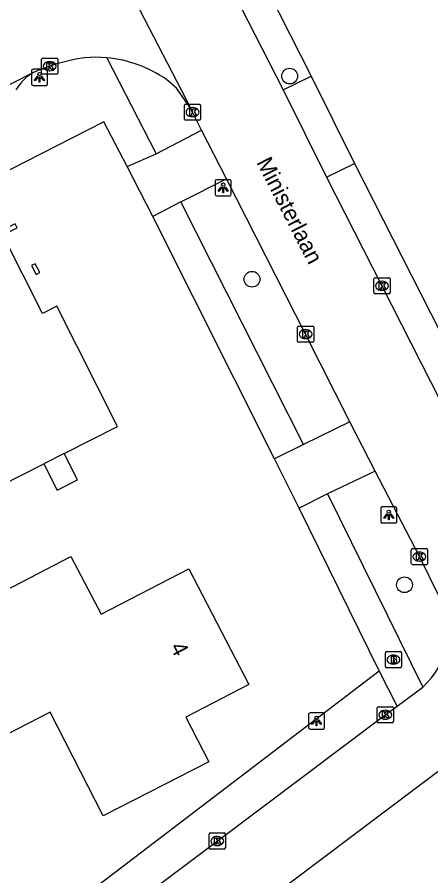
# Model space of a CAD drawing. Extents: x 162722 to 165099, y 384721 to 386283.
# Drawn here: x 163676.9 to 163702.6, y 384930.1 to 384983.4 of the extents above; entities that cross this region are included whole.
import ezdxf

# ---------------------------------------------------------------- set-up
doc = ezdxf.new("R2010")
doc.units = 0
for name, color, linetype in [('IMGEO_Boom', 7, 'Continuous'), ('IMGEO_Brandkraan', 7, 'Continuous'), ('IMGEO_Kolk', 7, 'Continuous'), ('IMGEO_Lichtpunt', 7, 'Continuous'), ('IMGEO_Openbare_ruimte_label', 7, 'Continuous'), ('IMGEO_Pand', 7, 'Continuous'), ('IMGEO_Pand_nummerreeks', 7, 'Continuous'), ('IMGEO_Parkeervlak_open', 7, 'Continuous'), ('IMGEO_Rijbaan_lokaal_open', 7, 'Continuous'), ('IMGEO_Voetpad_open', 7, 'Continuous')]:
    doc.layers.add(name, color=color, linetype=linetype)

msp = doc.modelspace()

# ---------------------------------------------------------------- linework, layer by layer
at = {"layer": 'IMGEO_Boom'}
for centre in [(163693.809, 384979.719), (163691.473, 384967.11), (163700.934, 384948.148)]:
    msp.add_circle(centre, 0.489, dxfattribs=at)
at = {"layer": 'IMGEO_Brandkraan'}
for p, q in [((163699.823, 384944.001), (163700.675, 384944.001)), ((163699.748, 384943.075), (163699.748, 384943.927)), ((163700.236, 384943.781), (163700.261, 384943.781)), ((163700.749, 384943.927), (163700.749, 384943.075)), ((163700.675, 384943.001), (163699.823, 384943.001)), ((163700.259, 384943.221), (163700.234, 384943.221))]:
    msp.add_line(p, q, dxfattribs=at)
for points in [[(163699.823, 384944.001), (163700.675, 384944.001)], [(163699.748, 384943.075), (163699.748, 384943.927)], [(163700.096, 384943.701), (163700.096, 384943.301), (163700.309, 384943.301)], [(163700.327, 384943.701), (163700.096, 384943.701)], [(163700.275, 384943.62), (163700.221, 384943.62), (163700.221, 384943.544)], [(163700.221, 384943.544), (163700.274, 384943.544)], [(163700.283, 384943.468), (163700.221, 384943.468), (163700.221, 384943.387)], [(163700.749, 384943.927), (163700.749, 384943.075)], [(163700.675, 384943.001), (163699.823, 384943.001)], [(163700.221, 384943.387), (163700.283, 384943.387)]]:
    msp.add_lwpolyline(points, dxfattribs=at)
for centre, radius, start, end in [((163699.825, 384943.925), 0.0765, 91.552, 178.448), ((163699.825, 384943.925), 0.0765, 91.552, 178.448), ((163700.673, 384943.925), 0.0765, 1.552, 88.448), ((163700.673, 384943.925), 0.0765, 1.552, 88.448), ((163700.276, 384943.582), 0.0379, 267.8285, 90.9355), ((163700.284, 384943.427), 0.0404, 269.8759, 90.5077), ((163700.331, 384943.556), 0.145, 59.4692, 91.5367), ((163700.356, 384943.603), 0.0922, 285.5137, 58.1501), ((163700.361, 384943.411), 0.105, 301.3115, 78.989), ((163699.825, 384943.077), 0.0765, 181.552, 268.448), ((163699.825, 384943.077), 0.0765, 181.552, 268.448), ((163700.315, 384943.552), 0.251, 268.6676, 293.5347), ((163700.673, 384943.077), 0.0765, 271.552, 358.448), ((163700.673, 384943.077), 0.0765, 271.552, 358.448)]:
    msp.add_arc(centre, radius, start, end, dxfattribs=at)
for centre, major_axis, ratio, start_param, end_param in [((163700.235, 384943.501), (-0.387, 0.002), 0.722429, 4.712389, 7.853982), ((163700.26, 384943.501), (-0.39, 0.002), 0.717154, 1.570796, 4.712389)]:
    msp.add_ellipse(centre, major_axis=major_axis, ratio=ratio, start_param=start_param, end_param=end_param, dxfattribs=at)
at = {"layer": 'IMGEO_Kolk'}
for p, q in [((163678.427, 384979.908), (163678.427, 384980.76)), ((163678.502, 384980.834), (163679.354, 384980.834)), ((163679.428, 384980.76), (163679.428, 384979.908)), ((163678.915, 384980.614), (163678.94, 384980.614)), ((163679.354, 384979.834), (163678.502, 384979.834)), ((163678.938, 384980.054), (163678.913, 384980.054)), ((163687.288, 384977.056), (163687.288, 384977.908)), ((163687.363, 384977.982), (163688.215, 384977.982)), ((163687.776, 384977.762), (163687.801, 384977.762)), ((163688.289, 384977.908), (163688.289, 384977.056)), ((163688.215, 384976.982), (163687.363, 384976.982)), ((163687.799, 384977.202), (163687.774, 384977.202)), ((163699.033, 384966.278), (163699.033, 384967.13)), ((163699.108, 384967.204), (163699.96, 384967.204)), ((163699.521, 384966.984), (163699.546, 384966.984)), ((163700.034, 384967.13), (163700.034, 384966.278)), ((163699.544, 384966.424), (163699.519, 384966.424)), ((163699.96, 384966.204), (163699.108, 384966.204)), ((163694.375, 384964.202), (163695.227, 384964.202)), ((163694.3, 384963.276), (163694.3, 384964.128)), ((163694.788, 384963.982), (163694.813, 384963.982)), ((163695.301, 384964.128), (163695.301, 384963.276)), ((163695.227, 384963.202), (163694.375, 384963.202)), ((163694.811, 384963.422), (163694.786, 384963.422)), ((163701.43, 384950.395), (163702.282, 384950.395)), ((163701.355, 384949.469), (163701.355, 384950.321)), ((163701.843, 384950.175), (163701.868, 384950.175)), ((163702.356, 384950.321), (163702.356, 384949.469)), ((163702.282, 384949.395), (163701.43, 384949.395)), ((163701.866, 384949.615), (163701.841, 384949.615)), ((163699.239, 384939.655), (163699.239, 384940.507)), ((163699.314, 384940.581), (163700.166, 384940.581)), ((163699.727, 384940.361), (163699.752, 384940.361)), ((163700.24, 384940.507), (163700.24, 384939.655)), ((163699.75, 384939.801), (163699.725, 384939.801)), ((163700.166, 384939.581), (163699.314, 384939.581)), ((163688.895, 384932.743), (163689.747, 384932.743)), ((163688.82, 384931.817), (163688.82, 384932.669)), ((163689.308, 384932.523), (163689.333, 384932.523)), ((163689.821, 384932.669), (163689.821, 384931.817)), ((163689.747, 384931.743), (163688.895, 384931.743)), ((163689.331, 384931.963), (163689.306, 384931.963))]:
    msp.add_line(p, q, dxfattribs=at)
for points in [[(163678.427, 384979.908), (163678.427, 384980.76)], [(163678.502, 384980.834), (163679.354, 384980.834)], [(163679.428, 384980.76), (163679.428, 384979.908)], [(163678.748, 384980.534), (163678.871, 384980.534), (163678.871, 384980.383), (163679.001, 384980.534), (163679.165, 384980.534), (163679.019, 384980.383), (163679.172, 384980.134), (163679.02, 384980.134), (163678.935, 384980.298), (163678.871, 384980.231), (163678.871, 384980.134), (163678.748, 384980.134), (163678.748, 384980.534)], [(163679.354, 384979.834), (163678.502, 384979.834)], [(163687.288, 384977.056), (163687.288, 384977.908)], [(163687.363, 384977.982), (163688.215, 384977.982)], [(163687.609, 384977.682), (163687.732, 384977.682), (163687.732, 384977.531), (163687.862, 384977.682), (163688.026, 384977.682), (163687.88, 384977.531), (163688.033, 384977.282), (163687.881, 384977.282), (163687.796, 384977.446), (163687.732, 384977.379), (163687.732, 384977.282), (163687.609, 384977.282), (163687.609, 384977.682)], [(163688.289, 384977.908), (163688.289, 384977.056)], [(163688.215, 384976.982), (163687.363, 384976.982)], [(163699.033, 384966.278), (163699.033, 384967.13)], [(163699.108, 384967.204), (163699.96, 384967.204)], [(163699.354, 384966.904), (163699.477, 384966.904), (163699.477, 384966.753), (163699.607, 384966.904), (163699.771, 384966.904), (163699.625, 384966.753), (163699.778, 384966.504), (163699.626, 384966.504), (163699.541, 384966.668), (163699.477, 384966.601), (163699.477, 384966.504), (163699.354, 384966.504), (163699.354, 384966.904)], [(163700.034, 384967.13), (163700.034, 384966.278)], [(163699.96, 384966.204), (163699.108, 384966.204)], [(163694.375, 384964.202), (163695.227, 384964.202)], [(163694.3, 384963.276), (163694.3, 384964.128)], [(163694.621, 384963.902), (163694.744, 384963.902), (163694.744, 384963.751), (163694.874, 384963.902), (163695.038, 384963.902), (163694.892, 384963.751), (163695.045, 384963.502), (163694.893, 384963.502), (163694.808, 384963.666), (163694.744, 384963.599), (163694.744, 384963.502), (163694.621, 384963.502), (163694.621, 384963.902)], [(163695.301, 384964.128), (163695.301, 384963.276)], [(163695.227, 384963.202), (163694.375, 384963.202)], [(163701.43, 384950.395), (163702.282, 384950.395)], [(163701.355, 384949.469), (163701.355, 384950.321)], [(163701.676, 384950.095), (163701.799, 384950.095), (163701.799, 384949.944), (163701.929, 384950.095), (163702.093, 384950.095), (163701.947, 384949.944), (163702.1, 384949.695), (163701.948, 384949.695), (163701.863, 384949.859), (163701.799, 384949.792), (163701.799, 384949.695), (163701.676, 384949.695), (163701.676, 384950.095)], [(163702.356, 384950.321), (163702.356, 384949.469)], [(163702.282, 384949.395), (163701.43, 384949.395)], [(163699.239, 384939.655), (163699.239, 384940.507)], [(163699.314, 384940.581), (163700.166, 384940.581)], [(163699.56, 384940.281), (163699.683, 384940.281), (163699.683, 384940.13), (163699.813, 384940.281), (163699.977, 384940.281), (163699.831, 384940.13), (163699.984, 384939.881), (163699.832, 384939.881), (163699.747, 384940.045), (163699.683, 384939.978), (163699.683, 384939.881), (163699.56, 384939.881), (163699.56, 384940.281)], [(163700.24, 384940.507), (163700.24, 384939.655)], [(163700.166, 384939.581), (163699.314, 384939.581)], [(163688.895, 384932.743), (163689.747, 384932.743)], [(163688.82, 384931.817), (163688.82, 384932.669)], [(163689.141, 384932.443), (163689.264, 384932.443), (163689.264, 384932.292), (163689.394, 384932.443), (163689.558, 384932.443), (163689.412, 384932.292), (163689.565, 384932.043), (163689.413, 384932.043), (163689.328, 384932.207), (163689.264, 384932.14), (163689.264, 384932.043), (163689.141, 384932.043), (163689.141, 384932.443)], [(163689.821, 384932.669), (163689.821, 384931.817)], [(163689.747, 384931.743), (163688.895, 384931.743)]]:
    msp.add_lwpolyline(points, dxfattribs=at)
for centre, start, end in [((163678.504, 384980.758), 91.552, 178.448), ((163678.504, 384980.758), 91.552, 178.448), ((163679.352, 384980.758), 1.552, 88.448), ((163679.352, 384980.758), 1.552, 88.448), ((163678.504, 384979.91), 181.552, 268.448), ((163678.504, 384979.91), 181.552, 268.448), ((163679.352, 384979.91), 271.552, 358.448), ((163679.352, 384979.91), 271.552, 358.448), ((163687.365, 384977.906), 91.552, 178.448), ((163687.365, 384977.906), 91.552, 178.448), ((163688.213, 384977.906), 1.552, 88.448), ((163688.213, 384977.906), 1.552, 88.448), ((163687.365, 384977.058), 181.552, 268.448), ((163687.365, 384977.058), 181.552, 268.448), ((163688.213, 384977.058), 271.552, 358.448), ((163688.213, 384977.058), 271.552, 358.448), ((163699.11, 384967.128), 91.552, 178.448), ((163699.11, 384967.128), 91.552, 178.448), ((163699.958, 384967.128), 1.552, 88.448), ((163699.958, 384967.128), 1.552, 88.448), ((163699.11, 384966.28), 181.552, 268.448), ((163699.11, 384966.28), 181.552, 268.448), ((163699.958, 384966.28), 271.552, 358.448), ((163699.958, 384966.28), 271.552, 358.448), ((163694.377, 384964.126), 91.552, 178.448), ((163694.377, 384964.126), 91.552, 178.448), ((163695.225, 384964.126), 1.552, 88.448), ((163695.225, 384964.126), 1.552, 88.448), ((163694.377, 384963.278), 181.552, 268.448), ((163694.377, 384963.278), 181.552, 268.448), ((163695.225, 384963.278), 271.552, 358.448), ((163695.225, 384963.278), 271.552, 358.448), ((163701.432, 384950.319), 91.552, 178.448), ((163701.432, 384950.319), 91.552, 178.448), ((163702.28, 384950.319), 1.552, 88.448), ((163702.28, 384950.319), 1.552, 88.448), ((163701.432, 384949.471), 181.552, 268.448), ((163701.432, 384949.471), 181.552, 268.448), ((163702.28, 384949.471), 271.552, 358.448), ((163702.28, 384949.471), 271.552, 358.448), ((163699.316, 384940.505), 91.552, 178.448), ((163699.316, 384940.505), 91.552, 178.448), ((163700.164, 384940.505), 1.552, 88.448), ((163700.164, 384940.505), 1.552, 88.448), ((163699.316, 384939.657), 181.552, 268.448), ((163699.316, 384939.657), 181.552, 268.448), ((163700.164, 384939.657), 271.552, 358.448), ((163700.164, 384939.657), 271.552, 358.448), ((163688.897, 384932.667), 91.552, 178.448), ((163688.897, 384932.667), 91.552, 178.448), ((163689.745, 384932.667), 1.552, 88.448), ((163689.745, 384932.667), 1.552, 88.448), ((163688.897, 384931.819), 181.552, 268.448), ((163688.897, 384931.819), 181.552, 268.448), ((163689.745, 384931.819), 271.552, 358.448), ((163689.745, 384931.819), 271.552, 358.448)]:
    msp.add_arc(centre, 0.0765, start, end, dxfattribs=at)
for centre, major_axis, ratio, start_param, end_param in [((163678.914, 384980.334), (-0.387, 0.002), 0.722429, 4.712389, 7.853982), ((163678.939, 384980.334), (-0.39, 0.002), 0.717154, 1.570796, 4.712389), ((163687.775, 384977.482), (-0.387, 0.002), 0.722429, 4.712389, 7.853982), ((163687.8, 384977.482), (-0.39, 0.002), 0.717154, 1.570796, 4.712389), ((163699.52, 384966.704), (-0.387, 0.002), 0.722429, 4.712389, 7.853982), ((163699.545, 384966.704), (-0.39, 0.002), 0.717154, 1.570796, 4.712389), ((163694.787, 384963.702), (-0.387, 0.002), 0.722429, 4.712389, 7.853982), ((163694.812, 384963.702), (-0.39, 0.002), 0.717154, 1.570796, 4.712389), ((163701.842, 384949.895), (-0.387, 0.002), 0.722429, 4.712389, 7.853982), ((163701.867, 384949.895), (-0.39, 0.002), 0.717154, 1.570796, 4.712389), ((163699.726, 384940.081), (-0.387, 0.002), 0.722429, 4.712389, 7.853982), ((163699.751, 384940.081), (-0.39, 0.002), 0.717154, 1.570796, 4.712389), ((163689.307, 384932.243), (-0.387, 0.002), 0.722429, 4.712389, 7.853982), ((163689.332, 384932.243), (-0.39, 0.002), 0.717154, 1.570796, 4.712389)]:
    msp.add_ellipse(centre, major_axis=major_axis, ratio=ratio, start_param=start_param, end_param=end_param, dxfattribs=at)
at = {"layer": 'IMGEO_Lichtpunt'}
for p, q in [((163677.802, 384980.045), (163677.802, 384979.238)), ((163677.802, 384980.045), (163677.802, 384979.238)), ((163678.704, 384980.14), (163677.896, 384980.14)), ((163678.704, 384980.14), (163677.896, 384980.14)), ((163678.798, 384979.238), (163678.798, 384980.045)), ((163678.798, 384979.238), (163678.798, 384980.045)), ((163677.896, 384979.144), (163678.704, 384979.144)), ((163677.896, 384979.144), (163678.704, 384979.144)), ((163690.091, 384973.283), (163689.283, 384973.283)), ((163690.091, 384973.283), (163689.283, 384973.283)), ((163689.189, 384973.188), (163689.189, 384972.381)), ((163689.189, 384973.188), (163689.189, 384972.381)), ((163690.185, 384972.381), (163690.185, 384973.188)), ((163690.185, 384972.381), (163690.185, 384973.188)), ((163689.283, 384972.287), (163690.091, 384972.287)), ((163689.283, 384972.287), (163690.091, 384972.287)), ((163699.459, 384952.883), (163699.459, 384952.076)), ((163699.459, 384952.883), (163699.459, 384952.076)), ((163700.361, 384952.978), (163699.553, 384952.978)), ((163700.361, 384952.978), (163699.553, 384952.978)), ((163700.455, 384952.076), (163700.455, 384952.883)), ((163700.455, 384952.076), (163700.455, 384952.883)), ((163699.553, 384951.982), (163700.361, 384951.982)), ((163699.553, 384951.982), (163700.361, 384951.982)), ((163694.981, 384940.096), (163694.981, 384939.289)), ((163694.981, 384940.096), (163694.981, 384939.289)), ((163695.883, 384940.191), (163695.075, 384940.191)), ((163695.883, 384940.191), (163695.075, 384940.191)), ((163695.977, 384939.289), (163695.977, 384940.096)), ((163695.977, 384939.289), (163695.977, 384940.096)), ((163695.075, 384939.195), (163695.883, 384939.195)), ((163695.075, 384939.195), (163695.883, 384939.195))]:
    msp.add_line(p, q, dxfattribs=at)
for points in [[(163678.176, 384979.709), (163678.215, 384979.681), (163678.027, 384979.419), (163677.989, 384979.446), (163678.176, 384979.709)], [(163678.278, 384979.661), (163678.325, 384979.661), (163678.325, 384979.339), (163678.278, 384979.339), (163678.278, 384979.661)], [(163678.388, 384979.681), (163678.426, 384979.708), (163678.613, 384979.446), (163678.574, 384979.418), (163678.388, 384979.681)], [(163689.563, 384972.852), (163689.602, 384972.824), (163689.414, 384972.562), (163689.376, 384972.589), (163689.563, 384972.852)], [(163689.665, 384972.804), (163689.712, 384972.804), (163689.712, 384972.482), (163689.665, 384972.482), (163689.665, 384972.804)], [(163689.775, 384972.824), (163689.813, 384972.851), (163690, 384972.589), (163689.961, 384972.561), (163689.775, 384972.824)], [(163699.833, 384952.547), (163699.872, 384952.519), (163699.684, 384952.257), (163699.646, 384952.284), (163699.833, 384952.547)], [(163699.935, 384952.499), (163699.982, 384952.499), (163699.982, 384952.177), (163699.935, 384952.177), (163699.935, 384952.499)], [(163700.045, 384952.519), (163700.083, 384952.546), (163700.27, 384952.284), (163700.231, 384952.256), (163700.045, 384952.519)], [(163695.355, 384939.76), (163695.394, 384939.732), (163695.206, 384939.47), (163695.168, 384939.497), (163695.355, 384939.76)], [(163695.457, 384939.712), (163695.504, 384939.712), (163695.504, 384939.39), (163695.457, 384939.39), (163695.457, 384939.712)], [(163695.567, 384939.732), (163695.605, 384939.759), (163695.792, 384939.497), (163695.753, 384939.469), (163695.567, 384939.732)]]:
    msp.add_lwpolyline(points, dxfattribs=at)
for centre in [(163678.301, 384979.843), (163689.688, 384972.986), (163699.958, 384952.681), (163695.48, 384939.894)]:
    msp.add_circle(centre, 0.0994, dxfattribs=at)
for centre, start, end in [((163677.896, 384980.045), 90, 180), ((163677.896, 384980.045), 90, 180), ((163678.704, 384980.045), 0, 90), ((163678.704, 384980.045), 0, 90), ((163677.896, 384979.238), 180, 270), ((163677.896, 384979.238), 180, 270), ((163678.704, 384979.238), 270, 0), ((163678.704, 384979.238), 270, 360), ((163689.283, 384973.188), 90, 180), ((163689.283, 384973.188), 90, 180), ((163690.091, 384973.188), 0, 90), ((163690.091, 384973.188), 0, 90), ((163689.283, 384972.381), 180, 270), ((163689.283, 384972.381), 180, 270), ((163690.091, 384972.381), 270, 0), ((163690.091, 384972.381), 270, 360), ((163699.553, 384952.883), 90, 180), ((163699.553, 384952.883), 90, 180), ((163700.361, 384952.883), 0, 90), ((163700.361, 384952.883), 0, 90), ((163699.553, 384952.076), 180, 270), ((163699.553, 384952.076), 180, 270), ((163700.361, 384952.076), 270, 0), ((163700.361, 384952.076), 270, 360), ((163695.075, 384940.096), 90, 180), ((163695.075, 384940.096), 90, 180), ((163695.883, 384940.096), 0, 90), ((163695.883, 384940.096), 0, 90), ((163695.075, 384939.289), 180, 270), ((163695.075, 384939.289), 180, 270), ((163695.883, 384939.289), 270, 0), ((163695.883, 384939.289), 270, 360)]:
    msp.add_arc(centre, 0.0946, start, end, dxfattribs=at)
at = {"layer": 'IMGEO_Pand'}
for points in [[(163679.824, 384956.289), (163683.138, 384957.961), (163679.364, 384965.444), (163678.473, 384964.994), (163676.019, 384969.859), (163676.91, 384970.309), (163676.793, 384970.541), (163668.173, 384966.193), (163668.587, 384965.373), (163669.574, 384963.417), (163667.958, 384962.602), (163666.964, 384964.571), (163660.215, 384961.167), (163662.466, 384956.703), (163662.971, 384955.701), (163671.374, 384959.94), (163674.556, 384953.632), (163678.57, 384955.657)], [(163678.036, 384968.077), (163677.805, 384967.96), (163678.084, 384967.407), (163678.315, 384967.523), (163678.036, 384968.077)], [(163679.824, 384956.289), (163678.57, 384955.657)], [(163678.57, 384955.657), (163679.396, 384954.019), (163680.65, 384954.651), (163679.824, 384956.289)], [(163672.547, 384945.919), (163680.246, 384949.912), (163682.111, 384946.316), (163687.55, 384949.136), (163691.272, 384941.96), (163687.376, 384939.939), (163688.8, 384937.15), (163682.245, 384933.803), (163678.953, 384940.248), (163676.222, 384938.832), (163672.547, 384945.919)]]:
    msp.add_lwpolyline(points, dxfattribs=at)
at = {"layer": 'IMGEO_Parkeervlak_open'}
for points in [[(163688.473, 384992.888), (163695.133, 384979.723)], [(163697.839, 384974.289), (163705.48, 384959.251)]]:
    msp.add_lwpolyline(points, dxfattribs=at)
at = {"layer": 'IMGEO_Rijbaan_lokaal_open'}
for points in [[(163679.812, 384992.892), (163679.873, 384992.805), (163687.684, 384977.706)], [(163686.744, 384992.011), (163689.884, 384985.748), (163693.405, 384978.87)], [(163682.479, 384980.861), (163681.787, 384980.887), (163681.095, 384980.851), (163680.527, 384980.775), (163679.377, 384980.48), (163678.259, 384980.084), (163677.921, 384979.942)], [(163677.921, 384979.942), (163666.306, 384974.039), (163651.654, 384966.572), (163648.716, 384965.114)], [(163687.684, 384977.706), (163686.783, 384978.976), (163686.166, 384979.51)], [(163693.405, 384978.87), (163696.103, 384973.454)], [(163688.346, 384976.358), (163687.789, 384977.482), (163687.684, 384977.706)], [(163689.884, 384973.343), (163688.346, 384976.358)], [(163697.55, 384958.253), (163694.801, 384963.702), (163689.884, 384973.343)], [(163696.103, 384973.454), (163699.534, 384966.704), (163703.768, 384958.355)], [(163699.111, 384955.206), (163697.55, 384958.253)], [(163703.08, 384947.428), (163701.856, 384949.895), (163699.111, 384955.206)], [(163700.468, 384940.621), (163702.06, 384941.801)], [(163677.764, 384923.542), (163677.956, 384923.704), (163689.321, 384932.243), (163699.74, 384940.081), (163700.468, 384940.621)], [(163703.684, 384937.056), (163680.028, 384919.248)]]:
    msp.add_lwpolyline(points, dxfattribs=at)
for centre, radius, start, end in [((163681.688, 384972.996), 7.904, 55.4937, 84.2583), ((163699.026, 384945.257), 4.599, 311.2828, 28.1684)]:
    msp.add_arc(centre, radius, start, end, dxfattribs=at)
at = {"layer": 'IMGEO_Voetpad_open'}
for points in [[(163682.479, 384980.861), (163685.526, 384974.9)], [(163677.921, 384979.942), (163677.702, 384979.805), (163677.497, 384979.649), (163677.306, 384979.475), (163677.132, 384979.285), (163676.975, 384979.08), (163676.837, 384978.862)], [(163693.405, 384978.87), (163695.133, 384979.723)], [(163695.133, 384979.723), (163697.839, 384974.289)], [(163683.732, 384974.099), (163682.29, 384976.876), (163639.563, 384955.061), (163635.539, 384952.364), (163633.451, 384950.624), (163627.464, 384944.399)], [(163685.526, 384974.9), (163688.346, 384976.358)], [(163683.732, 384974.099), (163685.526, 384974.9)], [(163685.319, 384971.004), (163683.732, 384974.099)], [(163696.103, 384973.454), (163697.839, 384974.289)], [(163687.069, 384971.907), (163689.884, 384973.343)], [(163687.069, 384971.907), (163685.319, 384971.004)], [(163694.677, 384956.848), (163687.069, 384971.907)], [(163692.876, 384955.959), (163685.319, 384971.004)], [(163697.55, 384958.253), (163694.677, 384956.848)], [(163694.677, 384956.848), (163692.876, 384955.959)], [(163694.404, 384952.9), (163692.876, 384955.959)], [(163699.111, 384955.206), (163696.161, 384953.784)], [(163696.161, 384953.784), (163694.404, 384952.9)], [(163696.161, 384953.784), (163702.06, 384941.801)], [(163699.363, 384942.796), (163694.404, 384952.9)], [(163673.969, 384906.848), (163673.753, 384907.134), (163665.55, 384917.268), (163665.421, 384917.261), (163660.75, 384923.114), (163663.751, 384924.681), (163669.399, 384920.052), (163676.37, 384925.254), (163699.363, 384942.796)], [(163700.468, 384940.621), (163699.363, 384942.796)]]:
    msp.add_lwpolyline(points, dxfattribs=at)

# ---------------------------------------------------------------- texts
at = {"layer": 'IMGEO_Openbare_ruimte_label'}
msp.add_text('Ministerlaan', height=1, rotation=297.1797, dxfattribs=at).set_placement((163691.726, 384974.368))
at = {"layer": 'IMGEO_Pand_nummerreeks'}
msp.add_text('4', height=1, rotation=297.4146, dxfattribs=at).set_placement((163686.373, 384944.282))

doc.saveas('drawing.dxf')
